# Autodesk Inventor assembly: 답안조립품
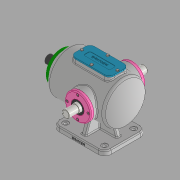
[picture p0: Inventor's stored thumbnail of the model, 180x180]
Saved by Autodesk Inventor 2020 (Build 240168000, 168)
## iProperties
Created: 2021-11
Part Number: 답안조립품
Document SubType Name: Assembly
Designer: Administrator
Author: Administrator
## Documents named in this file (14)
- C:\Users\Administrator\Desktop\711106V1023\답안조립품.iam
- C:\Users\Administrator\Desktop\711106V1023\본체.ipt
- C:\Users\Administrator\Desktop\711106V1023\베어링 6205.ipt
- 베어링 6205.ipt
- C:\Users\Administrator\Desktop\711106V1023\볼트 M4x0.7.ipt
- C:\Users\Administrator\Desktop\711106V1023\부시.ipt
- C:\Users\Administrator\Desktop\711106V1023\상부커버.ipt
- C:\Users\Administrator\Desktop\711106V1023\슬라이드 커버.ipt
- C:\Users\Administrator\Desktop\711106V1023\슬라이드.ipt
- C:\Users\Administrator\Desktop\711106V1023\오일실.ipt
- 오일실.ipt
- C:\Users\Administrator\Desktop\711106V1023\육각머리볼트 M4.ipt
- C:\Users\Administrator\Desktop\711106V1023\축 커버.ipt
- C:\Users\Administrator\Desktop\711106V1023\편심축.ipt
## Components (12 placed, 1 different names)
1. M4x0.7:1 — 각도:6
2. M4x0.7:3
3. M4x0.7:4
4. M4x0.7:5
5. M4x0.7:2 — 각도:5
6. M4x0.7:6
7. M4x0.7:7
8. M4x0.7:8
9. M4x0.7:9 — 각도:7
10. M4x0.7:10
11. M4x0.7:11
12. M4x0.7:12
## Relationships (3: Angle 3)
- 각도:5 [Angle]: M4x0.7:2
- 각도:6 [Angle]: M4x0.7:1
- 각도:7 [Angle]: M4x0.7:9
